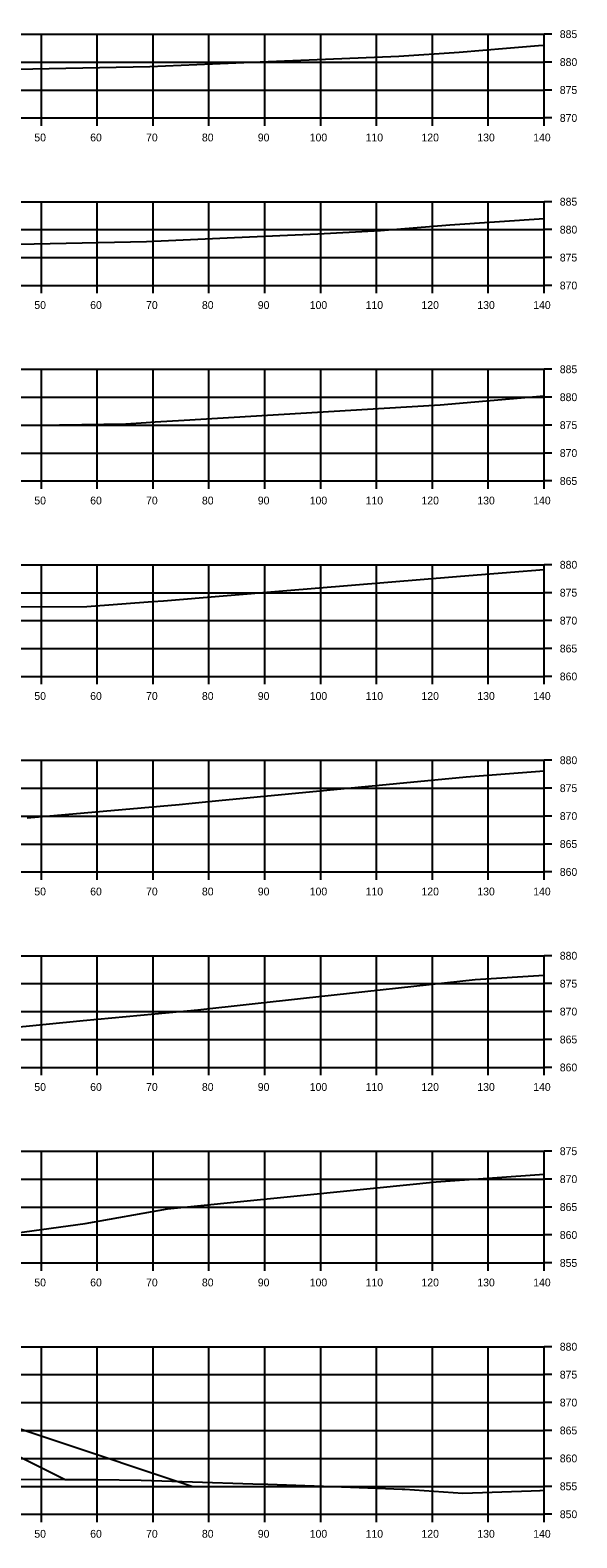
# Model space of a CAD drawing. Extents: x 1098669 to 1198896, y 698679 to 704410.
# Drawn here: x 1110829.2 to 1110927, y 701794.9 to 702064.8 of the extents above; entities that cross this region are included whole.
import ezdxf

# ---------------------------------------------------------------- set-up
doc = ezdxf.new("R2010")
doc.units = 0
for name, color, linetype in [('Proposed Surface', 7, 'Continuous'), ('R_Axis', 7, 'Continuous'), ('R_Axis Annot', 7, 'Continuous'), ('R_Grid', 7, 'Continuous'), ('R_Water', 7, 'Continuous')]:
    doc.layers.add(name, color=color, linetype=linetype)

msp = doc.modelspace()

# ---------------------------------------------------------------- linework, layer by layer
at = {"layer": 'Proposed Surface'}
for points in [[(1110809.13, 702057.49), (1110832.57, 702058.01), (1110850.59, 702058.37), (1110867.39, 702059.07), (1110895.13, 702060.19), (1110905.94, 702060.92), (1110914.39, 702061.62), (1110920.16, 702062.1), (1110921.16, 702062.18)], [(1110821.16, 702026.39), (1110849.97, 702027), (1110865.74, 702027.72), (1110880.64, 702028.37), (1110891.88, 702028.98), (1110904.26, 702029.98), (1110921.16, 702031.14)], [(1110814.79, 701993.81), (1110830.49, 701994.13), (1110846.3, 701994.34), (1110849.89, 701994.63), (1110851.52, 701994.75), (1110856.71, 701995.01), (1110892.55, 701997.14), (1110902.56, 701997.79), (1110921.16, 701999.38)], [(1110812.99, 701961.56), (1110839.28, 701961.64), (1110851.07, 701962.54), (1110853.04, 701962.69), (1110874.37, 701964.48), (1110905.48, 701967.01), (1110915.14, 701967.82), (1110921.16, 701968.31)], [(1110828.64, 701923.84), (1110855.84, 701926.22), (1110858.16, 701926.43), (1110862.9, 701926.9), (1110907.2, 701931.16), (1110921.16, 701932.23)], [(1110817.53, 701885.44), (1110838.66, 701887.55), (1110859.19, 701889.43), (1110878.09, 701891.54), (1110908.83, 701894.87), (1110921.16, 701895.67)], [(1110817.23, 701848.23), (1110838.97, 701851.16), (1110853.71, 701853.84), (1110891.21, 701857.57), (1110901.8, 701858.65), (1110921.16, 701860.05)], [(1110826.68, 701805.42), (1110835.43, 701805.36), (1110841.18, 701805.38), (1110849.02, 701805.23), (1110858.24, 701804.92), (1110869.01, 701804.56), (1110871.7, 701804.49), (1110883.32, 701804.09), (1110892.74, 701803.76), (1110895.75, 701803.63), (1110896.24, 701803.61), (1110906.62, 701802.91), (1110918.81, 701803.33), (1110920.41, 701803.36), (1110920.42, 701803.36), (1110921.16, 701803.43)]]:
    msp.add_lwpolyline(points, dxfattribs=at)
at = {"layer": 'R_Axis'}
for p, q in [((1110921.16, 702049.13), (1110921.16, 702064.13)), ((1110922.56, 702064.13), (1110921.16, 702064.13)), ((1110922.56, 702059.13), (1110921.16, 702059.13)), ((1110922.56, 702054.13), (1110921.16, 702054.13)), ((1110641.16, 702049.13), (1110921.16, 702049.13)), ((1110831.16, 702047.73), (1110831.16, 702049.13)), ((1110841.16, 702047.73), (1110841.16, 702049.13)), ((1110851.16, 702047.73), (1110851.16, 702049.13)), ((1110861.16, 702047.73), (1110861.16, 702049.13)), ((1110871.16, 702047.73), (1110871.16, 702049.13)), ((1110881.16, 702047.73), (1110881.16, 702049.13)), ((1110891.16, 702047.73), (1110891.16, 702049.13)), ((1110901.16, 702047.73), (1110901.16, 702049.13)), ((1110911.16, 702047.73), (1110911.16, 702049.13)), ((1110921.16, 702047.73), (1110921.16, 702049.13)), ((1110922.56, 702049.13), (1110921.16, 702049.13)), ((1110921.16, 702019.13), (1110921.16, 702034.13)), ((1110922.56, 702034.13), (1110921.16, 702034.13)), ((1110922.56, 702029.13), (1110921.16, 702029.13)), ((1110922.56, 702024.13), (1110921.16, 702024.13)), ((1110641.16, 702019.13), (1110921.16, 702019.13)), ((1110831.16, 702017.73), (1110831.16, 702019.13)), ((1110841.16, 702017.73), (1110841.16, 702019.13)), ((1110851.16, 702017.73), (1110851.16, 702019.13)), ((1110861.16, 702017.73), (1110861.16, 702019.13)), ((1110871.16, 702017.73), (1110871.16, 702019.13)), ((1110881.16, 702017.73), (1110881.16, 702019.13)), ((1110891.16, 702017.73), (1110891.16, 702019.13)), ((1110901.16, 702017.73), (1110901.16, 702019.13)), ((1110911.16, 702017.73), (1110911.16, 702019.13)), ((1110921.16, 702017.73), (1110921.16, 702019.13)), ((1110922.56, 702019.13), (1110921.16, 702019.13)), ((1110921.16, 701984.13), (1110921.16, 702004.13)), ((1110922.56, 702004.13), (1110921.16, 702004.13)), ((1110922.56, 701999.13), (1110921.16, 701999.13)), ((1110922.56, 701994.13), (1110921.16, 701994.13)), ((1110922.56, 701989.13), (1110921.16, 701989.13)), ((1110641.16, 701984.13), (1110921.16, 701984.13)), ((1110831.16, 701982.73), (1110831.16, 701984.13)), ((1110841.16, 701982.73), (1110841.16, 701984.13)), ((1110851.16, 701982.73), (1110851.16, 701984.13)), ((1110861.16, 701982.73), (1110861.16, 701984.13)), ((1110871.16, 701982.73), (1110871.16, 701984.13)), ((1110881.16, 701982.73), (1110881.16, 701984.13)), ((1110891.16, 701982.73), (1110891.16, 701984.13)), ((1110901.16, 701982.73), (1110901.16, 701984.13)), ((1110911.16, 701982.73), (1110911.16, 701984.13)), ((1110921.16, 701982.73), (1110921.16, 701984.13)), ((1110922.56, 701984.13), (1110921.16, 701984.13)), ((1110921.16, 701949.13), (1110921.16, 701969.13)), ((1110922.56, 701969.13), (1110921.16, 701969.13)), ((1110922.56, 701964.13), (1110921.16, 701964.13)), ((1110922.56, 701959.13), (1110921.16, 701959.13)), ((1110922.56, 701954.13), (1110921.16, 701954.13)), ((1110641.16, 701949.13), (1110921.16, 701949.13)), ((1110831.16, 701947.73), (1110831.16, 701949.13)), ((1110841.16, 701947.73), (1110841.16, 701949.13)), ((1110851.16, 701947.73), (1110851.16, 701949.13)), ((1110861.16, 701947.73), (1110861.16, 701949.13)), ((1110871.16, 701947.73), (1110871.16, 701949.13)), ((1110881.16, 701947.73), (1110881.16, 701949.13)), ((1110891.16, 701947.73), (1110891.16, 701949.13)), ((1110901.16, 701947.73), (1110901.16, 701949.13)), ((1110911.16, 701947.73), (1110911.16, 701949.13)), ((1110921.16, 701947.73), (1110921.16, 701949.13)), ((1110922.56, 701949.13), (1110921.16, 701949.13)), ((1110921.16, 701914.13), (1110921.16, 701934.13)), ((1110922.56, 701934.13), (1110921.16, 701934.13)), ((1110922.56, 701929.13), (1110921.16, 701929.13)), ((1110922.56, 701924.13), (1110921.16, 701924.13)), ((1110922.56, 701919.13), (1110921.16, 701919.13)), ((1110641.16, 701914.13), (1110921.16, 701914.13)), ((1110831.16, 701912.73), (1110831.16, 701914.13)), ((1110841.16, 701912.73), (1110841.16, 701914.13)), ((1110851.16, 701912.73), (1110851.16, 701914.13)), ((1110861.16, 701912.73), (1110861.16, 701914.13)), ((1110871.16, 701912.73), (1110871.16, 701914.13)), ((1110881.16, 701912.73), (1110881.16, 701914.13)), ((1110891.16, 701912.73), (1110891.16, 701914.13)), ((1110901.16, 701912.73), (1110901.16, 701914.13)), ((1110911.16, 701912.73), (1110911.16, 701914.13)), ((1110921.16, 701912.73), (1110921.16, 701914.13)), ((1110922.56, 701914.13), (1110921.16, 701914.13)), ((1110921.16, 701879.13), (1110921.16, 701899.13)), ((1110922.56, 701899.13), (1110921.16, 701899.13)), ((1110922.56, 701894.13), (1110921.16, 701894.13)), ((1110922.56, 701889.13), (1110921.16, 701889.13)), ((1110922.56, 701884.13), (1110921.16, 701884.13)), ((1110641.16, 701879.13), (1110921.16, 701879.13)), ((1110831.16, 701877.73), (1110831.16, 701879.13)), ((1110841.16, 701877.73), (1110841.16, 701879.13)), ((1110851.16, 701877.73), (1110851.16, 701879.13)), ((1110861.16, 701877.73), (1110861.16, 701879.13)), ((1110871.16, 701877.73), (1110871.16, 701879.13)), ((1110881.16, 701877.73), (1110881.16, 701879.13)), ((1110891.16, 701877.73), (1110891.16, 701879.13)), ((1110901.16, 701877.73), (1110901.16, 701879.13)), ((1110911.16, 701877.73), (1110911.16, 701879.13)), ((1110921.16, 701877.73), (1110921.16, 701879.13)), ((1110922.56, 701879.13), (1110921.16, 701879.13)), ((1110921.16, 701844.13), (1110921.16, 701864.13)), ((1110922.56, 701864.13), (1110921.16, 701864.13)), ((1110922.56, 701859.13), (1110921.16, 701859.13)), ((1110922.56, 701854.13), (1110921.16, 701854.13)), ((1110922.56, 701849.13), (1110921.16, 701849.13)), ((1110641.16, 701844.13), (1110921.16, 701844.13)), ((1110831.16, 701842.73), (1110831.16, 701844.13)), ((1110841.16, 701842.73), (1110841.16, 701844.13)), ((1110851.16, 701842.73), (1110851.16, 701844.13)), ((1110861.16, 701842.73), (1110861.16, 701844.13)), ((1110871.16, 701842.73), (1110871.16, 701844.13)), ((1110881.16, 701842.73), (1110881.16, 701844.13)), ((1110891.16, 701842.73), (1110891.16, 701844.13)), ((1110901.16, 701842.73), (1110901.16, 701844.13)), ((1110911.16, 701842.73), (1110911.16, 701844.13)), ((1110921.16, 701842.73), (1110921.16, 701844.13)), ((1110922.56, 701844.13), (1110921.16, 701844.13)), ((1110921.16, 701799.13), (1110921.16, 701829.13)), ((1110922.56, 701829.13), (1110921.16, 701829.13)), ((1110922.56, 701824.13), (1110921.16, 701824.13)), ((1110922.56, 701819.13), (1110921.16, 701819.13)), ((1110922.56, 701814.13), (1110921.16, 701814.13)), ((1110922.56, 701809.13), (1110921.16, 701809.13)), ((1110922.56, 701804.13), (1110921.16, 701804.13)), ((1110641.16, 701799.13), (1110921.16, 701799.13)), ((1110831.16, 701797.73), (1110831.16, 701799.13)), ((1110841.16, 701797.73), (1110841.16, 701799.13)), ((1110851.16, 701797.73), (1110851.16, 701799.13)), ((1110861.16, 701797.73), (1110861.16, 701799.13)), ((1110871.16, 701797.73), (1110871.16, 701799.13)), ((1110881.16, 701797.73), (1110881.16, 701799.13)), ((1110891.16, 701797.73), (1110891.16, 701799.13)), ((1110901.16, 701797.73), (1110901.16, 701799.13)), ((1110911.16, 701797.73), (1110911.16, 701799.13)), ((1110921.16, 701797.73), (1110921.16, 701799.13)), ((1110922.56, 701799.13), (1110921.16, 701799.13))]:
    msp.add_line(p, q, dxfattribs=at)
at = {"layer": 'R_Grid'}
for p, q in [((1110641.16, 702064.13), (1110921.16, 702064.13)), ((1110831.16, 702049.13), (1110831.16, 702064.13)), ((1110841.16, 702049.13), (1110841.16, 702064.13)), ((1110851.16, 702049.13), (1110851.16, 702064.13)), ((1110861.16, 702049.13), (1110861.16, 702064.13)), ((1110871.16, 702049.13), (1110871.16, 702064.13)), ((1110881.16, 702049.13), (1110881.16, 702064.13)), ((1110891.16, 702049.13), (1110891.16, 702064.13)), ((1110901.16, 702049.13), (1110901.16, 702064.13)), ((1110911.16, 702049.13), (1110911.16, 702064.13)), ((1110921.16, 702049.13), (1110921.16, 702064.13)), ((1110641.16, 702059.13), (1110921.16, 702059.13)), ((1110641.16, 702054.13), (1110921.16, 702054.13)), ((1110641.16, 702049.13), (1110921.16, 702049.13)), ((1110641.16, 702034.13), (1110921.16, 702034.13)), ((1110831.16, 702019.13), (1110831.16, 702034.13)), ((1110841.16, 702019.13), (1110841.16, 702034.13)), ((1110851.16, 702019.13), (1110851.16, 702034.13)), ((1110861.16, 702019.13), (1110861.16, 702034.13)), ((1110871.16, 702019.13), (1110871.16, 702034.13)), ((1110881.16, 702019.13), (1110881.16, 702034.13)), ((1110891.16, 702019.13), (1110891.16, 702034.13)), ((1110901.16, 702019.13), (1110901.16, 702034.13)), ((1110911.16, 702019.13), (1110911.16, 702034.13)), ((1110921.16, 702019.13), (1110921.16, 702034.13)), ((1110641.16, 702029.13), (1110921.16, 702029.13)), ((1110641.16, 702024.13), (1110921.16, 702024.13)), ((1110641.16, 702019.13), (1110921.16, 702019.13)), ((1110641.16, 702004.13), (1110921.16, 702004.13)), ((1110831.16, 701984.13), (1110831.16, 702004.13)), ((1110841.16, 701984.13), (1110841.16, 702004.13)), ((1110851.16, 701984.13), (1110851.16, 702004.13)), ((1110861.16, 701984.13), (1110861.16, 702004.13)), ((1110871.16, 701984.13), (1110871.16, 702004.13)), ((1110881.16, 701984.13), (1110881.16, 702004.13)), ((1110891.16, 701984.13), (1110891.16, 702004.13)), ((1110901.16, 701984.13), (1110901.16, 702004.13)), ((1110911.16, 701984.13), (1110911.16, 702004.13)), ((1110921.16, 701984.13), (1110921.16, 702004.13)), ((1110641.16, 701999.13), (1110921.16, 701999.13)), ((1110641.16, 701994.13), (1110921.16, 701994.13)), ((1110641.16, 701989.13), (1110921.16, 701989.13)), ((1110641.16, 701984.13), (1110921.16, 701984.13)), ((1110641.16, 701969.13), (1110921.16, 701969.13)), ((1110831.16, 701949.13), (1110831.16, 701969.13)), ((1110841.16, 701949.13), (1110841.16, 701969.13)), ((1110851.16, 701949.13), (1110851.16, 701969.13)), ((1110861.16, 701949.13), (1110861.16, 701969.13)), ((1110871.16, 701949.13), (1110871.16, 701969.13)), ((1110881.16, 701949.13), (1110881.16, 701969.13)), ((1110891.16, 701949.13), (1110891.16, 701969.13)), ((1110901.16, 701949.13), (1110901.16, 701969.13)), ((1110911.16, 701949.13), (1110911.16, 701969.13)), ((1110921.16, 701949.13), (1110921.16, 701969.13)), ((1110641.16, 701964.13), (1110921.16, 701964.13)), ((1110641.16, 701959.13), (1110921.16, 701959.13)), ((1110641.16, 701954.13), (1110921.16, 701954.13)), ((1110641.16, 701949.13), (1110921.16, 701949.13)), ((1110641.16, 701934.13), (1110921.16, 701934.13)), ((1110831.16, 701914.13), (1110831.16, 701934.13)), ((1110841.16, 701914.13), (1110841.16, 701934.13)), ((1110851.16, 701914.13), (1110851.16, 701934.13)), ((1110861.16, 701914.13), (1110861.16, 701934.13)), ((1110871.16, 701914.13), (1110871.16, 701934.13)), ((1110881.16, 701914.13), (1110881.16, 701934.13)), ((1110891.16, 701914.13), (1110891.16, 701934.13)), ((1110901.16, 701914.13), (1110901.16, 701934.13)), ((1110911.16, 701914.13), (1110911.16, 701934.13)), ((1110921.16, 701914.13), (1110921.16, 701934.13)), ((1110641.16, 701929.13), (1110921.16, 701929.13)), ((1110641.16, 701924.13), (1110921.16, 701924.13)), ((1110641.16, 701919.13), (1110921.16, 701919.13)), ((1110641.16, 701914.13), (1110921.16, 701914.13)), ((1110641.16, 701899.13), (1110921.16, 701899.13)), ((1110831.16, 701879.13), (1110831.16, 701899.13)), ((1110841.16, 701879.13), (1110841.16, 701899.13)), ((1110851.16, 701879.13), (1110851.16, 701899.13)), ((1110861.16, 701879.13), (1110861.16, 701899.13)), ((1110871.16, 701879.13), (1110871.16, 701899.13)), ((1110881.16, 701879.13), (1110881.16, 701899.13)), ((1110891.16, 701879.13), (1110891.16, 701899.13)), ((1110901.16, 701879.13), (1110901.16, 701899.13)), ((1110911.16, 701879.13), (1110911.16, 701899.13)), ((1110921.16, 701879.13), (1110921.16, 701899.13)), ((1110641.16, 701894.13), (1110921.16, 701894.13)), ((1110641.16, 701889.13), (1110921.16, 701889.13)), ((1110641.16, 701884.13), (1110921.16, 701884.13)), ((1110641.16, 701879.13), (1110921.16, 701879.13)), ((1110641.16, 701864.13), (1110921.16, 701864.13)), ((1110831.16, 701844.13), (1110831.16, 701864.13)), ((1110841.16, 701844.13), (1110841.16, 701864.13)), ((1110851.16, 701844.13), (1110851.16, 701864.13)), ((1110861.16, 701844.13), (1110861.16, 701864.13)), ((1110871.16, 701844.13), (1110871.16, 701864.13)), ((1110881.16, 701844.13), (1110881.16, 701864.13)), ((1110891.16, 701844.13), (1110891.16, 701864.13)), ((1110901.16, 701844.13), (1110901.16, 701864.13)), ((1110911.16, 701844.13), (1110911.16, 701864.13)), ((1110921.16, 701844.13), (1110921.16, 701864.13)), ((1110641.16, 701859.13), (1110921.16, 701859.13)), ((1110641.16, 701854.13), (1110921.16, 701854.13)), ((1110641.16, 701849.13), (1110921.16, 701849.13)), ((1110641.16, 701844.13), (1110921.16, 701844.13)), ((1110641.16, 701829.13), (1110921.16, 701829.13)), ((1110831.16, 701799.13), (1110831.16, 701829.13)), ((1110841.16, 701799.13), (1110841.16, 701829.13)), ((1110851.16, 701799.13), (1110851.16, 701829.13)), ((1110861.16, 701799.13), (1110861.16, 701829.13)), ((1110871.16, 701799.13), (1110871.16, 701829.13)), ((1110881.16, 701799.13), (1110881.16, 701829.13)), ((1110891.16, 701799.13), (1110891.16, 701829.13)), ((1110901.16, 701799.13), (1110901.16, 701829.13)), ((1110911.16, 701799.13), (1110911.16, 701829.13)), ((1110921.16, 701799.13), (1110921.16, 701829.13)), ((1110641.16, 701824.13), (1110921.16, 701824.13)), ((1110641.16, 701819.13), (1110921.16, 701819.13)), ((1110641.16, 701814.13), (1110921.16, 701814.13)), ((1110641.16, 701809.13), (1110921.16, 701809.13)), ((1110641.16, 701804.13), (1110921.16, 701804.13)), ((1110641.16, 701799.13), (1110921.16, 701799.13))]:
    msp.add_line(p, q, dxfattribs=at)
at = {"layer": 'R_Water'}
for points in [[(1110806.23, 701821.47), (1110858.25, 701804.13)], [(1110812.66, 701816.72), (1110835.39, 701805.36)]]:
    msp.add_lwpolyline(points, dxfattribs=at)

# ---------------------------------------------------------------- texts
at = {"layer": 'R_Axis Annot'}
for s, p in [('885', (1110923.96, 702063.43)), ('880', (1110923.96, 702058.43)), ('875', (1110923.96, 702053.43)), ('870', (1110923.96, 702048.43)), ('50', (1110829.9, 702044.93)), ('60', (1110839.9, 702044.93)), ('70', (1110849.9, 702044.93)), ('80', (1110859.9, 702044.93)), ('90', (1110869.9, 702044.93)), ('100', (1110879.2, 702044.93)), ('110', (1110889.2, 702044.93)), ('120', (1110899.2, 702044.93)), ('130', (1110909.2, 702044.93)), ('140', (1110919.2, 702044.93)), ('885', (1110923.96, 702033.43)), ('880', (1110923.96, 702028.43)), ('875', (1110923.96, 702023.43)), ('870', (1110923.96, 702018.43)), ('50', (1110829.9, 702014.93)), ('60', (1110839.9, 702014.93)), ('70', (1110849.9, 702014.93)), ('80', (1110859.9, 702014.93)), ('90', (1110869.9, 702014.93)), ('100', (1110879.2, 702014.93)), ('110', (1110889.2, 702014.93)), ('120', (1110899.2, 702014.93)), ('130', (1110909.2, 702014.93)), ('140', (1110919.2, 702014.93)), ('885', (1110923.96, 702003.43)), ('880', (1110923.96, 701998.43)), ('875', (1110923.96, 701993.43)), ('870', (1110923.96, 701988.43)), ('865', (1110923.96, 701983.43)), ('50', (1110829.9, 701979.93)), ('60', (1110839.9, 701979.93)), ('70', (1110849.9, 701979.93)), ('80', (1110859.9, 701979.93)), ('90', (1110869.9, 701979.93)), ('100', (1110879.2, 701979.93)), ('110', (1110889.2, 701979.93)), ('120', (1110899.2, 701979.93)), ('130', (1110909.2, 701979.93)), ('140', (1110919.2, 701979.93)), ('880', (1110923.96, 701968.43)), ('875', (1110923.96, 701963.43)), ('870', (1110923.96, 701958.43)), ('865', (1110923.96, 701953.43)), ('860', (1110923.96, 701948.43)), ('50', (1110829.9, 701944.93)), ('60', (1110839.9, 701944.93)), ('70', (1110849.9, 701944.93)), ('80', (1110859.9, 701944.93)), ('90', (1110869.9, 701944.93)), ('100', (1110879.2, 701944.93)), ('110', (1110889.2, 701944.93)), ('120', (1110899.2, 701944.93)), ('130', (1110909.2, 701944.93)), ('140', (1110919.2, 701944.93)), ('880', (1110923.96, 701933.43)), ('875', (1110923.96, 701928.43)), ('870', (1110923.96, 701923.43)), ('865', (1110923.96, 701918.43)), ('860', (1110923.96, 701913.43)), ('50', (1110829.9, 701909.93)), ('60', (1110839.9, 701909.93)), ('70', (1110849.9, 701909.93)), ('80', (1110859.9, 701909.93)), ('90', (1110869.9, 701909.93)), ('100', (1110879.2, 701909.93)), ('110', (1110889.2, 701909.93)), ('120', (1110899.2, 701909.93)), ('130', (1110909.2, 701909.93)), ('140', (1110919.2, 701909.93)), ('880', (1110923.96, 701898.43)), ('875', (1110923.96, 701893.43)), ('870', (1110923.96, 701888.43)), ('865', (1110923.96, 701883.43)), ('860', (1110923.96, 701878.43)), ('50', (1110829.9, 701874.93)), ('60', (1110839.9, 701874.93)), ('70', (1110849.9, 701874.93)), ('80', (1110859.9, 701874.93)), ('90', (1110869.9, 701874.93)), ('100', (1110879.2, 701874.93)), ('110', (1110889.2, 701874.93)), ('120', (1110899.2, 701874.93)), ('130', (1110909.2, 701874.93)), ('140', (1110919.2, 701874.93)), ('875', (1110923.96, 701863.43)), ('870', (1110923.96, 701858.43)), ('865', (1110923.96, 701853.43)), ('860', (1110923.96, 701848.43)), ('855', (1110923.96, 701843.43)), ('50', (1110829.9, 701839.93)), ('60', (1110839.9, 701839.93)), ('70', (1110849.9, 701839.93)), ('80', (1110859.9, 701839.93)), ('90', (1110869.9, 701839.93)), ('100', (1110879.2, 701839.93)), ('110', (1110889.2, 701839.93)), ('120', (1110899.2, 701839.93)), ('130', (1110909.2, 701839.93)), ('140', (1110919.2, 701839.93)), ('880', (1110923.96, 701828.43)), ('875', (1110923.96, 701823.43)), ('870', (1110923.96, 701818.43)), ('865', (1110923.96, 701813.43)), ('860', (1110923.96, 701808.43)), ('855', (1110923.96, 701803.43)), ('850', (1110923.96, 701798.43)), ('50', (1110829.9, 701794.93)), ('60', (1110839.9, 701794.93)), ('70', (1110849.9, 701794.93)), ('80', (1110859.9, 701794.93)), ('90', (1110869.9, 701794.93)), ('100', (1110879.2, 701794.93)), ('110', (1110889.2, 701794.93)), ('120', (1110899.2, 701794.93)), ('130', (1110909.2, 701794.93)), ('140', (1110919.2, 701794.93))]:
    msp.add_text(s, height=1.4, dxfattribs=at).set_placement(p)

doc.saveas('drawing.dxf')
